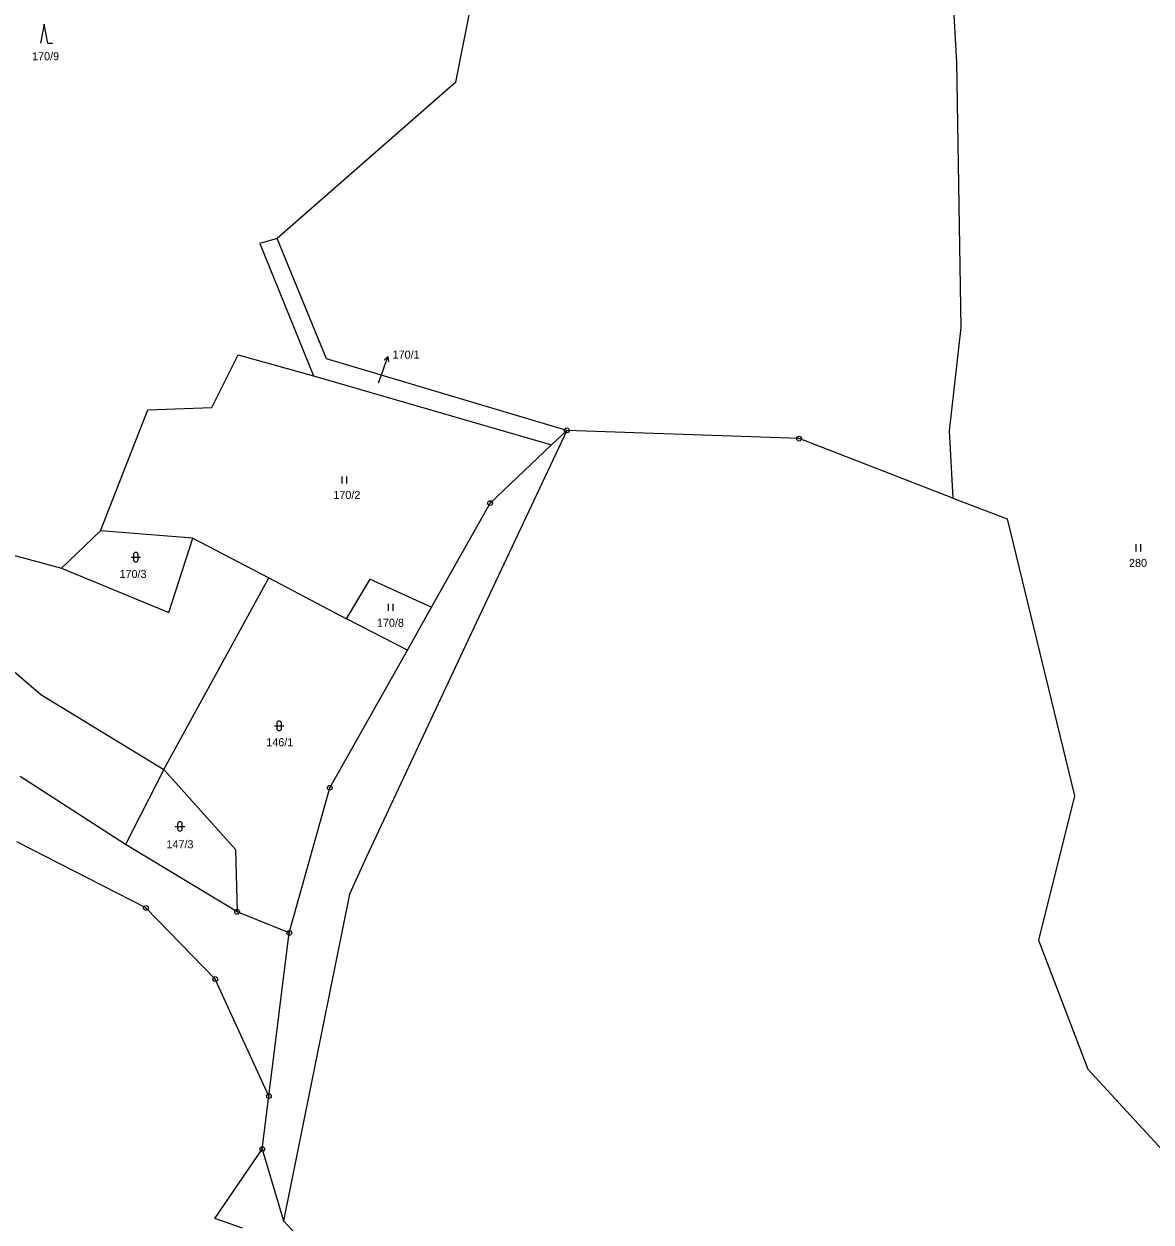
# Model space of a CAD drawing. Extents: x -765428 to -762163, y -1107632 to -1104975.
# Drawn here: x -763268.9 to -763031.1, y -1106721.8 to -1106469 of the extents above; entities that cross this region are included whole.
import ezdxf
from ezdxf.enums import TextEntityAlignment as Align

# ---------------------------------------------------------------- set-up
doc = ezdxf.new("R2010")
doc.units = 0
doc.header["$LTSCALE"] = 0.68
for name, color, linetype, lineweight in [('1', 7, 'Continuous', 25), ('3', 7, 'Continuous', 25), ('4', 7, 'Continuous', 13), ('7', 7, 'Continuous', 13), ('8', 7, 'Continuous', 25)]:
    doc.layers.add(name, color=color, linetype=linetype, lineweight=lineweight)
doc.layers.add('2', color=7, linetype='Continuous')

msp = doc.modelspace()

# ---------------------------------------------------------------- linework, layer by layer
at = {"layer": '1'}
for p, q in [((-763074.11, -1106444.61), (-763072.15, -1106477.08)), ((-763177.79, -1106481.32), (-763174.46, -1106464.63)), ((-763072.15, -1106477.08), (-763071.26, -1106533.05)), ((-763219.17, -1106515.36), (-763207.81, -1106543.28)), ((-763205.07, -1106539.7), (-763215.48, -1106514.27)), ((-763071.26, -1106533.05), (-763073.72, -1106554.89)), ((-763229.28, -1106549.94), (-763223.71, -1106538.81)), ((-763223.71, -1106538.81), (-763207.81, -1106543.28)), ((-763154.38, -1106554.77), (-763205.07, -1106539.7)), ((-763207.81, -1106543.28), (-763157.63, -1106557.85)), ((-763252.74, -1106575.97), (-763242.78, -1106550.43)), ((-763242.78, -1106550.43), (-763229.28, -1106549.94)), ((-763157.63, -1106557.85), (-763154.38, -1106554.77)), ((-763105.38, -1106556.52), (-763154.38, -1106554.77)), ((-763073.72, -1106554.89), (-763072.95, -1106569.06)), ((-763170.56, -1106570.12), (-763157.63, -1106557.85)), ((-763072.95, -1106569.06), (-763105.38, -1106556.52)), ((-763182.93, -1106592.08), (-763170.56, -1106570.12)), ((-763072.95, -1106569.06), (-763061.46, -1106573.44)), ((-763061.46, -1106573.44), (-763047.29, -1106631.9)), ((-763252.74, -1106575.97), (-763261, -1106583.86)), ((-763233.29, -1106577.49), (-763252.74, -1106575.97)), ((-763281.23, -1106578.39), (-763261, -1106583.86)), ((-763238.31, -1106593.22), (-763233.29, -1106577.49)), ((-763233.29, -1106577.49), (-763217.27, -1106585.92)), ((-763261, -1106583.86), (-763238.31, -1106593.22)), ((-763239.39, -1106626.33), (-763217.27, -1106585.92)), ((-763217.27, -1106585.92), (-763200.87, -1106594.55)), ((-763200.87, -1106594.55), (-763195.85, -1106586.14)), ((-763195.85, -1106586.14), (-763182.93, -1106592.08)), ((-763188.02, -1106601.12), (-763182.93, -1106592.08)), ((-763284.2, -1106594.34), (-763265.37, -1106610.51)), ((-763188.02, -1106601.12), (-763200.87, -1106594.55)), ((-763204.4, -1106630.19), (-763188.02, -1106601.12)), ((-763265.37, -1106610.51), (-763239.39, -1106626.33)), ((-763239.39, -1106626.33), (-763247.51, -1106642.16)), ((-763239.39, -1106626.33), (-763224.28, -1106643.24)), ((-763247.51, -1106642.16), (-763269.72, -1106627.78)), ((-763212.93, -1106660.83), (-763204.4, -1106630.19)), ((-763047.29, -1106631.9), (-763054.89, -1106662.38)), ((-763243.17, -1106655.54), (-763270.44, -1106641.61)), ((-763223.94, -1106656.37), (-763247.51, -1106642.16)), ((-763224.28, -1106643.24), (-763223.94, -1106656.37)), ((-763228.56, -1106670.55), (-763243.17, -1106655.54)), ((-763212.93, -1106660.83), (-763223.94, -1106656.37)), ((-763217.23, -1106695.24), (-763212.93, -1106660.83)), ((-763054.89, -1106662.38), (-763044.45, -1106689.56)), ((-763217.23, -1106695.24), (-763228.56, -1106670.55)), ((-763044.45, -1106689.56), (-763025.55, -1106710.08)), ((-763218.63, -1106706.43), (-763217.23, -1106695.24)), ((-763228.66, -1106721.05), (-763218.63, -1106706.43)), ((-763218.63, -1106706.43), (-763214.13, -1106721.59)), ((-763222.77, -1106723.14), (-763228.66, -1106721.05)), ((-763214.13, -1106721.59), (-763153.95, -1106786.57))]:
    msp.add_line(p, q, dxfattribs=at)
msp.add_lwpolyline([(-763177.79, -1106481.32), (-763215.48, -1106514.27), (-763219.17, -1106515.36)], dxfattribs=at)
at = {"layer": '3'}
for p, q in [((-763263.89, -1106473.05), (-763262.894, -1106473.05)), ((-763201.801, -1106565.98), (-763201.801, -1106564.48)), ((-763200.8, -1106565.98), (-763200.8, -1106564.48)), ((-763034.281, -1106580.3), (-763034.281, -1106578.8)), ((-763033.28, -1106580.3), (-763033.28, -1106578.8)), ((-763245.811, -1106581.041), (-763245.811, -1106582.042)), ((-763244.809, -1106582.042), (-763244.809, -1106581.041)), ((-763246.311, -1106581.541), (-763244.309, -1106581.541)), ((-763192.001, -1106592.85), (-763192.001, -1106591.35)), ((-763191, -1106592.85), (-763191, -1106591.35)), ((-763215.571, -1106616.631), (-763215.571, -1106617.632)), ((-763214.569, -1106617.632), (-763214.569, -1106616.631)), ((-763216.071, -1106617.131), (-763214.069, -1106617.131)), ((-763237.001, -1106638.351), (-763234.999, -1106638.351)), ((-763236.501, -1106637.851), (-763236.501, -1106638.852)), ((-763235.499, -1106638.852), (-763235.499, -1106637.851))]:
    msp.add_line(p, q, dxfattribs=at)
msp.add_lwpolyline([(-763263.89, -1106473.05), (-763264.64, -1106469.05), (-763265.39, -1106473.05)], dxfattribs=at)
for centre, start, end in [((-763245.31, -1106581.0409), 0, 180), ((-763245.31, -1106582.0409), 180, 359.98789), ((-763215.07, -1106616.6309), 0, 180), ((-763215.07, -1106617.6309), 180, 359.98789), ((-763236, -1106637.8509), 0, 180), ((-763236, -1106638.8509), 180, 359.98789)]:
    msp.add_arc(centre, 0.5, start, end, dxfattribs=at)
at = {"layer": '4'}
for p, q in [((-763154.38, -1106554.77), (-763175.77, -1106600.18)), ((-763175.77, -1106600.18), (-763196.68, -1106644.89)), ((-763196.68, -1106644.89), (-763200.21, -1106652.64)), ((-763200.21, -1106652.64), (-763214.13, -1106721.59))]:
    msp.add_line(p, q, dxfattribs=at)
at = {"layer": '7'}
msp.add_line((-763192.124, -1106539.22), (-763192.937, -1106539.99), dxfattribs=at)
msp.add_lwpolyline([(-763194.14, -1106544.77), (-763193.15, -1106542.04), (-763192.124, -1106539.22), (-763191.996, -1106540.332)], dxfattribs=at)
at = {"layer": '8'}
for centre, radius in [((-763154.38, -1106554.7699), 0.5), ((-763154.38, -1106554.7699), 0.0303), ((-763105.38, -1106556.5199), 0.5), ((-763105.38, -1106556.5199), 0.0303), ((-763170.56, -1106570.1199), 0.5), ((-763170.56, -1106570.1199), 0.0303), ((-763204.4, -1106630.1899), 0.5), ((-763204.4, -1106630.1899), 0.0303), ((-763243.17, -1106655.5399), 0.5), ((-763243.17, -1106655.5399), 0.0303), ((-763223.94, -1106656.3699), 0.5), ((-763223.94, -1106656.3699), 0.0303), ((-763212.93, -1106660.8299), 0.5), ((-763212.93, -1106660.8299), 0.0303), ((-763228.56, -1106670.5499), 0.5), ((-763228.56, -1106670.5499), 0.0303), ((-763217.23, -1106695.2399), 0.5), ((-763217.23, -1106695.2399), 0.0303), ((-763218.63, -1106706.4299), 0.5), ((-763218.63, -1106706.4299), 0.0303)]:
    msp.add_circle(centre, radius, dxfattribs=at)

# ---------------------------------------------------------------- texts
at = {"layer": '2'}
for s, p in [('170/9', (-763264.35, -1106476.675)), ('146/1', (-763214.93, -1106621.425)), ('147/3', (-763236, -1106642.965))]:
    msp.add_text(s, height=1.7, dxfattribs=at).set_placement(p, align=Align.CENTER)
for s, p in [('170/1', (-763191.13, -1106539.645)), ('170/2', (-763203.63, -1106569.255)), ('280', (-763035.78, -1106583.595)), ('170/3', (-763248.75, -1106585.925)), ('170/8', (-763194.44, -1106596.225))]:
    msp.add_text(s, height=1.7, dxfattribs=at).set_placement(p)

doc.saveas('drawing.dxf')
